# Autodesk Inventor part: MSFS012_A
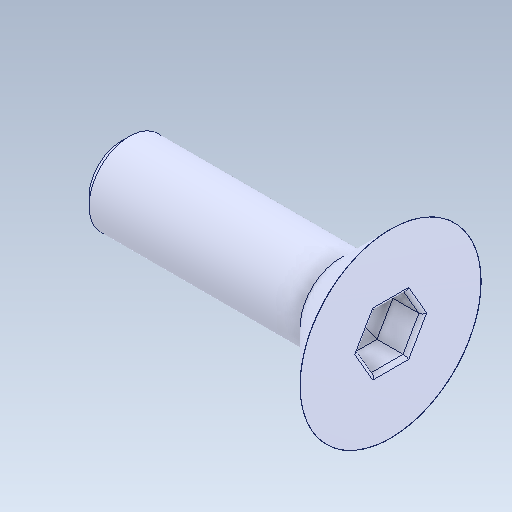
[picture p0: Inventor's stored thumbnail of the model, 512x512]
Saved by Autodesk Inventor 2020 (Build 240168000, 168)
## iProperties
Created: 2017-09
Part Number: MSFS012_A
Material: Générique
Document SubType Name: Modeling
Designer: bruno
Density: 1 g/cm^3
Appearance: Par défaut
Author: bruno
Sending System: SolidWorks 2016
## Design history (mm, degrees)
feature "Importée1"
node "Solide1"
